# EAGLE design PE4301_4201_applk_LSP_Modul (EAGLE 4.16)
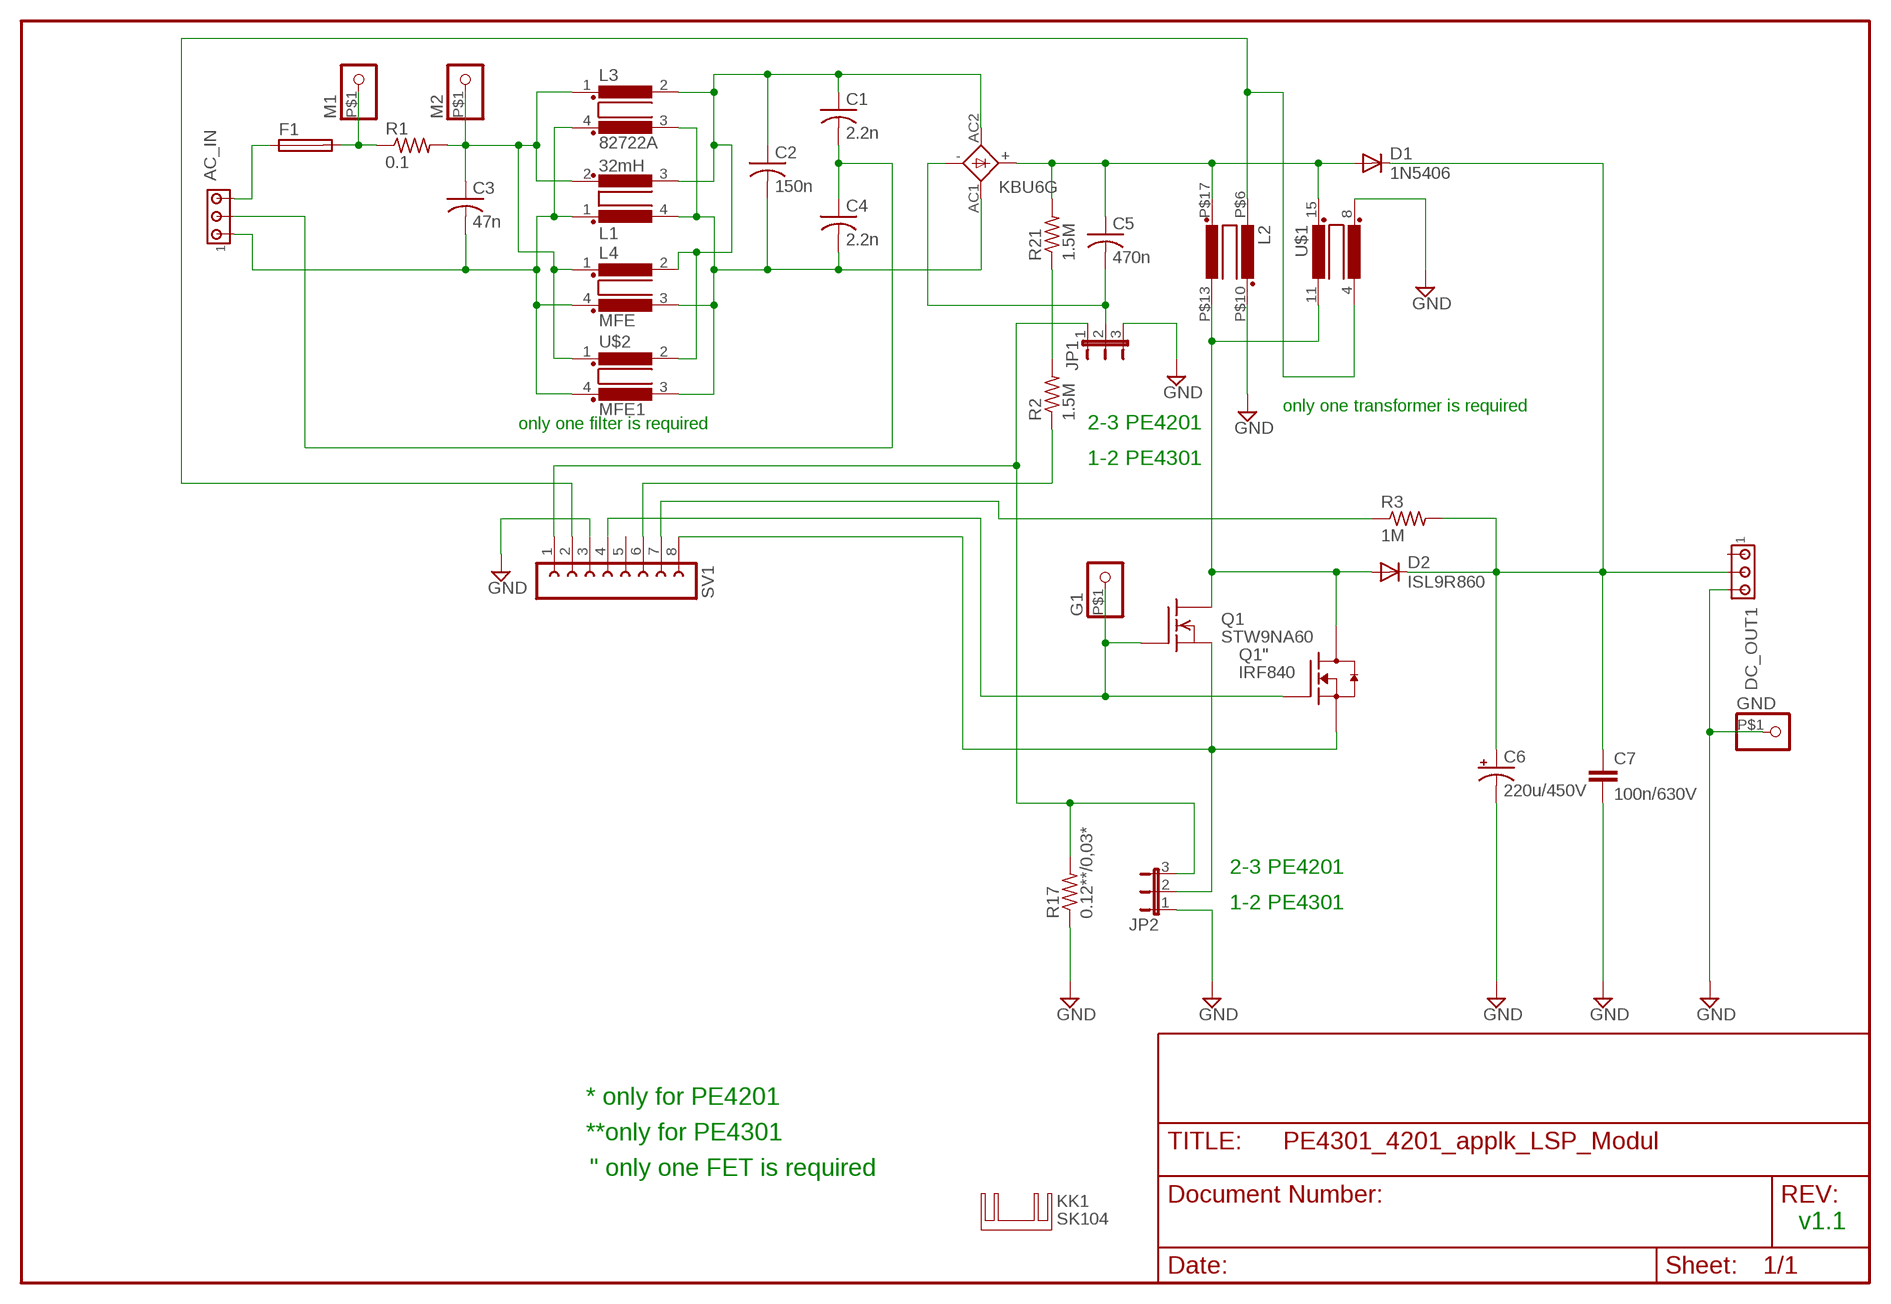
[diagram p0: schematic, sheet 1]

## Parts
AC_IN  KLEMME_3  [3MTA]
C1  2.2n  C2N2  [C2N2]
C2  150n  C-US150-084X183  [C150-084X183]
C3  47n  C-US102-064X133  [C102-064X133]
C4  2.2n  C2N2  [C2N2]
C5  470n  C-US150-084X183  [C150-084X183]
C6  220u/450V  CPOL-USE10-25  [EB25D]
C7  100n/630V  C15/6  [C15B6]
D1  1N5406  1N5624  [DO201-15]
D2  ISL9R860  BYT08P  [TO220ACS]
DC_OUT1  KLEMME_3  [3MTA]
F1  SH22,5A  [SH22,5A]
G1  PINHD  [LOETSTIFT]
GND  PINHD  [LOETSTIFT]
JP1  JP2E  [JP2]
JP2  JP2E  [JP2]
KBU6G  KBU  [KBU]
KK1  SK104  [SK104]
L1  32mH  VACT60405-R_2  [VACT60405-R]
L2  ETD49_SCH  [ETD49]
L3  82722A  [82722A]
L4  MFE  [MFE]
M1  PINHD  [LOETSTIFT]
M2  PINHD  [LOETSTIFT]
Q1  STW9NA60  FQA24N50  [TOP3V]
Q1"  IRF840  [TO220_V]
R1  0.1  R-US_0617/22  [0617/22]
R2  1.5M  R-US_0207/10  [0207/10]
R3  1M  R-US_0207/10  [0207/10]
R17  0.12**/0,03*  R-US_0617/22  [0617/22]
R21  1.5M  R-US_0207/10  [0207/10]
SV1  FE08-1  [FE08]
U$1  ETD39ETD39  [ETD29LS]
U$2  MFE1  [MFE1]

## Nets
B3: R3.1 SV1.7
GND: C6.- C7.2 DC_OUT1.3 GND.P$1 JP1.3 JP2.1 L2.P$10 R17.1 SV1.3 U$1.8
N$1: AC_IN.3 F1.1
N$2: AC_IN.1 C3.2 L1.1 L3.4 L4.4 U$2.4
N$3: C3.1 L1.2 L3.1 L4.1 M2.P$1 R1.2 U$2.1
N$4: C1.1 C2.1 KBU6G.AC2 L1.3 L3.2 L4.2 U$2.2
N$5: C2.2 C4.2 KBU6G.AC1 L1.4 L3.3 L4.3 U$2.3
N$6: R2.2 R21.1
N$7: R2.1 SV1.6
N$8: AC_IN.2 C1.2 C4.1
N$10: G1.P$1 Q1".1(G) Q1.G SV1.4
N$11: D2.A L2.P$13 Q1".2(D) Q1.D U$1.11
N$15: JP2.2 Q1".3(S) Q1.S SV1.8
N$17: C5.2 JP1.2 KBU6G.-
N$18: C6.+ C7.1 D1.C D2.C DC_OUT1.2 R3.2
N$20: F1.2 M1.P$1 R1.1
N$29: L2.P$6 SV1.2 U$1.4
N$30: C5.1 D1.A KBU6G.+ L2.P$17 R21.2 U$1.15
N$34: JP1.1 JP2.3 R17.2 SV1.1
Unconnected: DC_OUT1.1 SV1.5

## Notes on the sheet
- only one transformer is required
- only one filter is required | 2-3 PE4201
- 1-2 PE4301
- 2-3 PE4201
- 1-2 PE4301
- * only for PE4201
- **only for PE4301
- " only one FET is required
- v1.1

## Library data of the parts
AC_IN DC_OUT1 = PE4201:KLEMME_3: AMP connector
C1 C4 = PE4201:C2N2
C2 C3 C5 = rcl:C-US: CAPACITOR, American symbol
C6 = rcl:CPOL-US: POLARIZED CAPACITOR, American symbol
C7 = capacitor-wima:C: CAPACITOR
D1 = diode:1N5624: DIODE
D2 = diode:BYT08P: DIODE
F1 = fuse:SH22,5A: FUSE HOLDER
G1 GND M1 M2 = PE4201:PINHD: PIN HEADER
JP1 JP2 = jumper:JP2E: JUMPER
KBU6G = rectifier:KBU: DIOTEC RECTIFIER
KK1 = heatsink:SK104: HEATSINK
L1 = PE4201:VACT60405-R_2: FILTER
L2 = PE4201:ETD49_SCH
L3 = inductors:82722A: FILTER
L4 = inductors:MFE: FILTER
Q1 = PE4201:FQA24N50: N-Channel Enhancement MOSFET 400V; 12,5A; 0,4Ohm
Q1" = PE4201:IRF840
R1-R3 R17 R21 = rcl:R-US_: RESISTOR, American symbol
SV1 = con-lsta:FE08-1: FEMALE HEADER
U$1 = inductors:ETD39
U$2 = inductors:MFE1

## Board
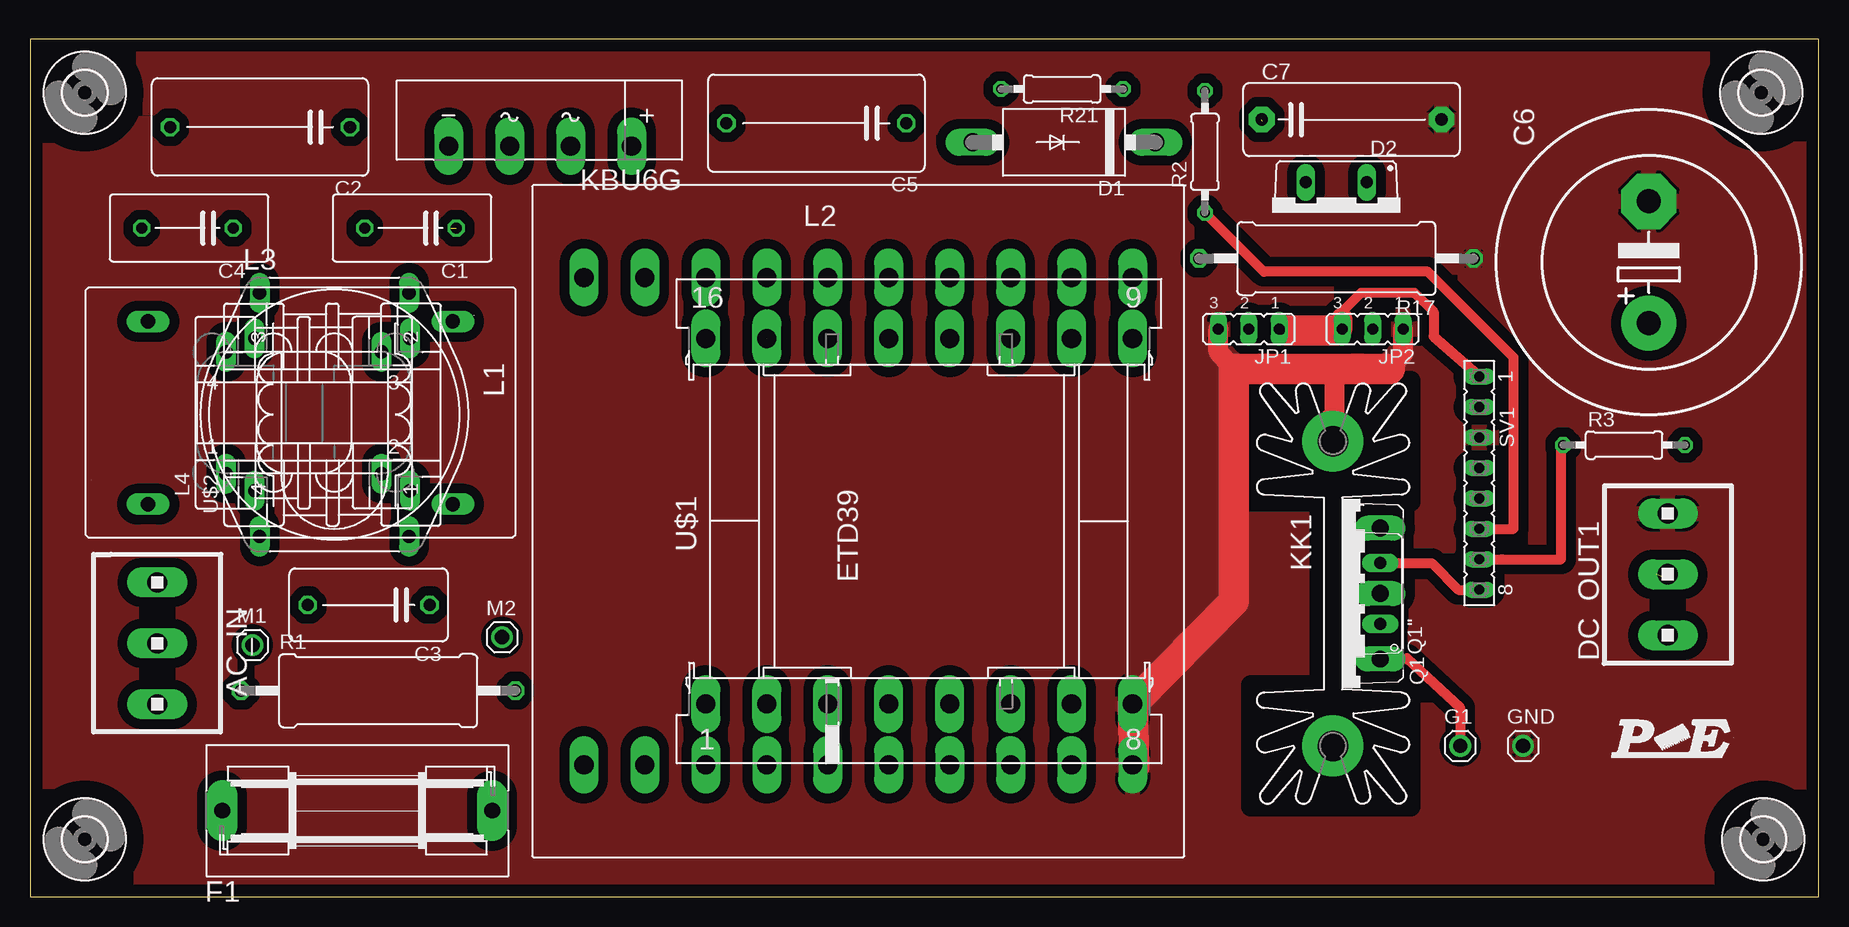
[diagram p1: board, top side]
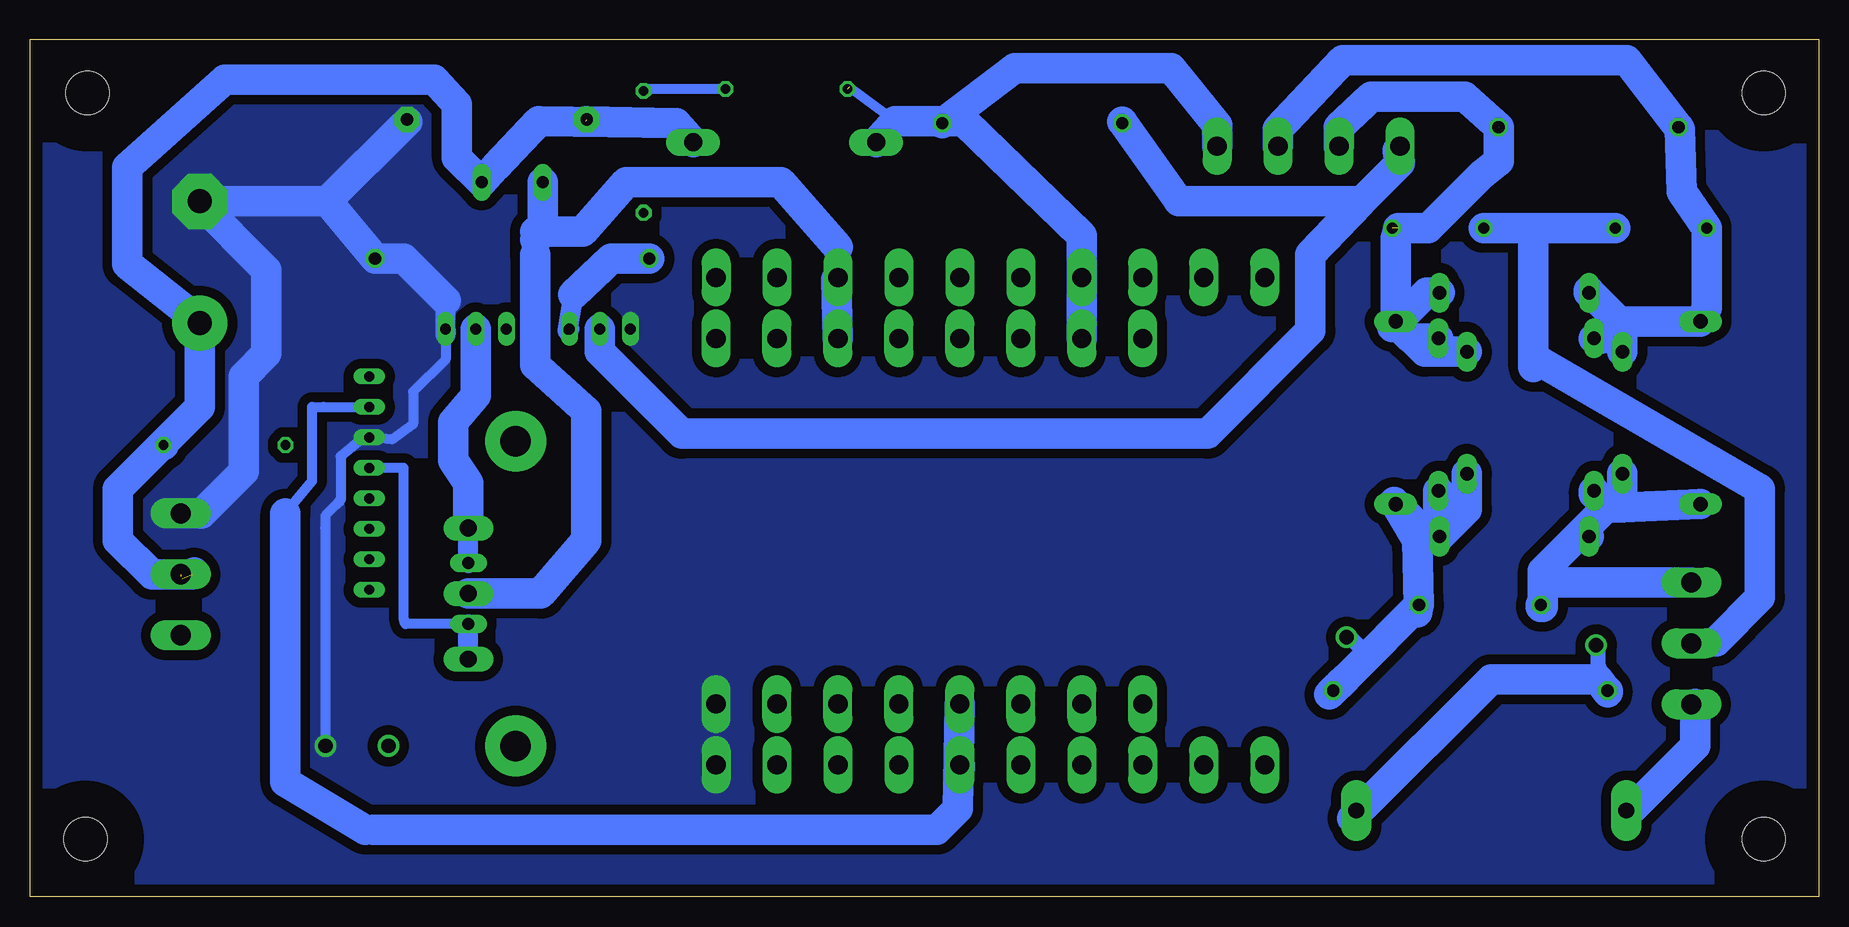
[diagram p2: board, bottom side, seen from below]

Size 149.05 x 71.48 mm. Coordinates in mm from the lower left corner, seen from the top.
Outline: 0,0 149.05,0 149.05,71.48 0,71.48 0,0
Copper layers (1*16): Top 0.035mm / dielectric 1.5mm / Bottom 0.035mm
Design rules "default": minimum track width 10mil, minimum drill 24mil, track to track 8mil, track to pad 8mil, pad to pad 8mil, via to via 8mil, smd to smd 8mil, copper to edge 40mil, drill to drill 8mil, minimum pad ring 10mil, minimum via ring 8mil, stop-mask expansion 4mil, vias tented up to drill 0mil, thermal gap 10mil

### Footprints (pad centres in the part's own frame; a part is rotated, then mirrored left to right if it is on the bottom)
3MTA = drill 1.676 long: 1 5.057,0; 2 -0.025,0; 3 -5.098,0
C2N2 = drill 0.914 octagon: 1 -3.81,0; 2 3.81,0
C150-084X183 = drill 1.016 octagon: 1 -7.493,0; 2 7.493,0
C102-064X133 = drill 1.016 octagon: 1 -5.08,0; 2 5.08,0
EB25D = drill 2.007 pad 4.597 round: + -5.08,0 | drill 2.007 pad 4.597 octagon: - 5.08,0
C15B6 = drill 1.016 pad 2.159 octagon: 1 -7.493,0; 2 7.493,0
DO201-15 = drill 1.499 long: A 7.62,0; C -7.62,0
TO220ACS = drill 1.016 long: A 2.54,-2.54; C -2.54,-2.54
SH22,5A = drill 1.321 pad 2.54 long: 1 -11.252,0; 2 11.252,0
LOETSTIFT = drill 1.2 round: P$1 0,0
JP2 = drill 0.914 long: 1 -2.54,0; 2 0,0; 3 2.54,0
KBU = drill 1.6 long: + -7.62,2.54; - 7.62,2.54; AC1 -2.54,2.54; AC2 2.54,2.54
SK104 = drill 2.54 pad 5.08 round: A2,5 -12.7,-0.762; B2,5 12.7,-0.762
VACT60405-R = drill 1.194 long: 1 12.983,7.624; 2 -12.413,7.624; 3 -12.413,-7.614; 4 12.983,-7.614
ETD49 = drill 1.6 long: P$1 15.24,-40.64; P$2 15.24,-35.56; P$3 15.24,-30.48; P$4 15.24,-25.4; P$5 15.24,-20.32; P$6 15.24,-15.24; P$7 15.24,-10.16; P$8 15.24,-5.08; P$9 15.24,0; P$10 15.24,5.08; P$11 -25.4,5.08; P$12 -25.4,0; P$13 -25.4,-5.08; P$14 -25.4,-10.16; P$15 -25.4,-15.24; P$16 -25.4,-20.32; P$17 -25.4,-25.4; P$18 -25.4,-30.48; P$19 -25.4,-35.56; P$20 -25.4,-40.64
82722A = drill 1.118 long: 1 10.16,6.223; 2 -10.16,6.223; 3 -10.16,-6.223; 4 10.16,-6.223
MFE = drill 1.118 long: 1 6.477,-5.08; 2 6.477,5.08; 3 -6.477,5.08; 4 -6.477,-5.08
TOP3V = drill 1.397 long: D 0,-3.175; G -5.461,-3.175; S 5.461,-3.175
TO220_V = drill 1.016 long: 1 -2.54,0; 2 0,0; 3 2.54,0
0617/22 = drill 1.016 octagon: 1 -11.43,0; 2 11.43,0
0207/10 = drill 0.813 octagon: 1 -5.08,0; 2 5.08,0
FE08 = drill 0.813 long: 1 -8.89,0; 2 -6.35,0; 3 -3.81,0; 4 -1.27,0; 5 1.27,0; 6 3.81,0; 7 6.35,0; 8 8.89,0
ETD29LS = drill 1.6 long: 1 -15.24,-17.78; 2 -10.16,-17.78; 3 -5.08,-17.78; 4 0,-17.78; 5 5.08,-17.78; 6 10.16,-17.78; 7 15.24,-17.78; 8 20.32,-17.78; 9 20.32,12.7; 10 15.24,12.7; 11 10.16,12.7; 12 5.08,12.7; 13 0,12.7; 14 -5.08,12.7; 15 -10.16,12.7; 16 -15.24,12.7; 25 5.08,-17.78
MFE1 = drill 1.118 long: 1 6.477,-6.35; 2 6.477,6.35; 3 -6.477,6.35; 4 -6.477,-6.35
3,6 = hole 3.6: 0,0

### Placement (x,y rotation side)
AC_IN  10.6,21.14 90 top
C1  31.71,55.74 180 top
C2  19.17,64.16 180 top
C3  28.22,24.31 180 top
C4  13.14,55.74 180 top
C5  65.53,64.47 180 top
C6  134.9,52.89 90 top
C7  110.13,64.79 0 top
D1  86.16,62.89 180 top
D2  108.86,57.01 180 top
DC_OUT1  136.49,26.85 270 top
F1  27.27,7.17 0 top
G1  119.18,12.56 0 top
GND  124.42,12.56 0 top
JP1  101.56,47.33 180 top
JP2  111.88,47.33 180 top
KBU6G  42.51,65.11 180 top
KK1  109.34,25.26 270 top
L1  22.82,40.34 180 top
L2  86.8,26.22 270 top
L3  25.36,40.19 270 top
L4  22.82,40.35 0 top
M1  18.54,20.98 0 top
M2  39.33,21.61 0 top
Q1  109.34,25.26 90 top
Q1"  112.52,25.26 90 top
R1  29.01,17.17 0 top
R2  97.91,62.09 90 top
R3  132.84,37.65 0 top
R17  108.86,53.2 180 top
R21  86,67.33 180 top
SV1  120.77,34.47 270 top
U$1  71.56,33.84 0 top
U$2  25.2,40.19 0 top
U$4  [LOGO]  132.52,10.98 0 top
U$5  [3,6]  144.27,67.02 0 top
U$6  [3,6]  4.57,67.02 0 top
U$7  [3,6]  4.57,4.79 0 top
U$8  [3,6]  144.43,4.79 0 top

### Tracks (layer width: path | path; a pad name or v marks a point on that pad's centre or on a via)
B3
  Top 0.813: 127.6,37.49 R3.1 127.6,37.65 127.6,37.49 | 127.6,28.12 122.68,28.12 SV1.7 | 127.6,28.12 | 127.6,37.49 | 127.6,28.12 127.6,37.49
GND
  Top 0.813: U$1.8 91.88,15.74 | 91.88,10.66 | 91.88,10.66 L2.P$10 | 91.88,10.66 92.04,10.82
  Top 1.676: JP1.3 99.02,45.43 100.29,44 | JP2.1 114.42,47.17 114.42,45.27 113.31,44 | 108.71,44 108.71,40.19 108.39,39.87
  Top 2.54: 113.31,44 108.71,44 100.29,44 100.29,24.63 U$1.8 92.04,10.82
  Bottom 0.813: U$1.8 91.88,15.74 | 114.42,47.17 JP2.1 114.42,44.79 117.12,42.09 117.12,39.39 118.87,38.12 SV1.3 121.25,38.28 123.15,36.69 123.15,33.2 123.15,33.04 123.47,32.73 124.42,31.77 124.42,30.66 124.42,30.82 GND.P$1
  Bottom 1.676: 114.42,46.85 | JP2.1 114.42,46.85 | 114.42,46.85 114.42,47.17 JP2.1 | JP2.1 114.42,49.71 | 117.63,64.6 C7.2 | C6.- 135.06,57.97
  Bottom 2.54: 124.26,57.97 R17.1 117.91,53.2 114.42,49.71 | 124.26,57.97 C6.- | 124.26,57.97 117.63,64.6 | 135.06,57.97 129.34,52.25 129.34,45.27 131.25,43.36 131.25,35.42 131.42,35.29 131.42,35.28 131.41,35.27 134.72,31.95 DC_OUT1.3
  pour Top (isolate 0.813): 0.28,71.46 148.55,71.46 arc90 148.87,71.78 148.87,0.34 arc90 149.03,0.18 0.12,0.18 0.12,71.3
  pour Bottom (isolate 0.813, no thermals): 0.12,71.46 148.87,71.46 149.19,71.14 149.19,0.02 149.03,0.18 0.12,0.18 0.12,71.3
N$1
  Bottom 1.27: AC_IN.3 10.3,16.04 10.28,16.06
  Bottom 2.54: F1.1 16.02,6.87 16,6.85 10.28,12.56 10.28,16.06
N$2
  Bottom 2.54: 22.98,24.31 C3.2 23.14,24.15 22.98,24.31 | AC_IN.1 22.98,26.19 22.98,24.31 | 22.98,24.31 22.98,24.15 | 17.75,32.4 16.3,32.46 | 16.3,32.46 L1.1 | 20.92,29.23 22.98,27.17 22.98,24.31 | 20.92,29.23 17.75,32.4 | 20.92,29.23 | L3.4 20.12,30.03 20.92,29.23 | 16.3,32.46 16.3,32.71 16.35,32.76 L4.4 | 17.75,32.4 17.75,32.56 17.74,32.57 18.73,33.55 U$2.4
N$3
  Bottom 1.27: 38.78,18.83 37.51,20.1 39.02,21.61 M2.P$1
  Bottom 2.54: C3.1 33.46,23.68 | C3.1 33.46,29.67 L1.2 35.24,32.76 | R1.2 39.97,17.64 39.33,18.28 40.76,16.85 38.78,18.83 C3.1 | 35.24,32.76 35.36,32.88 | 31.71,30.03 32.51,30.03 35.24,32.76 | L4.1 29.3,32.28 31.55,30.03 L3.1 31.71,30.03 | U$2.1 31.68,30.06 31.71,30.03
N$4  (2 unrouted)
  Bottom 1.676: KBU6G.AC2 39.65,62.41
  Bottom 2.54: L1.3 35.24,54.92 35.05,55.74 32.51,55.74 28.06,60.19 26.63,61.3 26.63,64.16 29.49,66.7 37.27,66.7 39.97,64.16 KBU6G.AC2 | L3.2 32.67,50.35 35.52,47.49 35.52,47.65 35.21,47.96 | 35.36,47.96 35.36,47.97 | 35.36,47.96 L1.3 | L4.2 32.82,45.43 35.05,47.65 | 35.05,47.65 35.36,47.96 | 35.05,47.65 35.24,47.84 L1.3 | U$2.2 33.94,46.54 35.05,47.65 | 35.21,47.96 35.21,47.97 | L1.3 35.21,47.96
N$5
  Bottom 1.676: C4.2 9.33,55.43 | L1.4 9.84,47.93
  Bottom 2.54: KBU6G.AC1 45.05,64 39.65,69.71 16,69.71 11.55,64 | 11.39,58.76 C4.2 9.33,49.08 9.84,47.93 16.31,47.93 | 11.39,58.76 | 11.39,58.76 11.55,64 | 19.14,50.47 19.17,50.51 | 19.14,50.47 L3.3 | 16.31,47.93 16.6,47.93 16.63,47.97 | 16.63,47.97 19.14,50.47 | 16.31,47.93 16.31,47.49 16.35,47.46 L4.3 | U$2.3 18.06,46.54 16.63,47.97 | C2.2 11.68,64.19 11.55,64 | 11.55,64
N$6
  Bottom 0.813: R2.2 | R21.1 97.91,67.33 R2.2
N$7
  Top 0.813: R2.1 102.83,52.09 116.49,52.09 116.8,51.78 123.63,44.95 123.63,30.66 SV1.6 | SV1.6
N$8
  Bottom 0.813: 23.78,44.95 23.78,44.16
  Bottom 1.27: AC_IN.2 10.6,21.14 8.54,21.3
  Bottom 2.54: 23.78,55.74 C4.1 | 23.78,55.74 C1.2 | 23.78,44.95 4.88,34 4.88,24.95 8.54,21.3 | 23.78,44.16 23.78,55.74
N$10
  Top 0.813: G1.P$1 119.18,15.74 114.74,19.87 112.83,19.87 112.52,20.18 Q1.G
  Bottom 0.813: Q1".1 117.76,22.72 117.91,23.2 117.91,35.74 SV1.4 | 112.52,20.18 112.52,19.87 Q1.G
  Bottom 1.676: 112.52,19.87 Q1".1
N$11
  Bottom 1.676: 81.88,51.46 L2.P$13 81.72,54.16 | 106.96,55.43 106.96,54.79 106.96,53.52 | Q1".2 112.68,25.42
  Bottom 2.54: U$1.11 81.88,51.46 | 81.72,54.16 86.48,59.55 99.34,59.55 102.99,55.43 106.96,55.43 | 106.96,53.52 106.96,44.31 102.67,40.5 102.67,29.71 106.48,25.26 Q1".2 | 106.96,54.79 | D2.A 106.33,55.43 106.96,54.79
N$15
  Top 0.813: SV1.8 119.03,25.58 116.8,27.8 Q1".3 112.52,27.65
  Bottom 0.813: 112.52,31.3 112.61,30.25 Q1.S
  Bottom 1.676: 112.52,31.3 | Q1".3 Q1.S 112.52,31.3
  Bottom 2.54: 112.52,31.3 112.52,34.47 113.79,36.38 113.79,39.55 111.88,41.77 JP2.2
N$17
  Bottom 1.676: 35.05,62.25 KBU6G.- | 58.03,64.6 C5.2
  Bottom 2.54: 38.06,57.97 34.89,61.14 35.05,62.25 | 38.06,57.97 53.3,57.97 58.03,64.6 | JP1.2 101.56,45.43 94.74,38.6 50.92,38.6 42.35,47.17 42.35,53.52 38.06,57.97
N$18  (3 unrouted)
  Bottom 1.676: 134.74,47.81 C6.+ | 136.49,26.69 136.35,26.51 | 102.67,64.63 102.99,64.32 | DC_OUT1.2
  Bottom 2.54: D1.C 95.21,64.48 | 95.21,64.48 106.64,64.63 110.29,60.82 D2.C 113.47,61.62 113.47,66.06 115.37,68.13 132.84,68.13 140.93,60.82 140.93,52.73 134.74,47.81 | 95.21,64.48 102.67,64.63 | C6.+ 134.9,40.82 137.92,37.81 | 137.92,37.81 141.73,34 141.73,29.71 138.87,26.85 135.54,26.85 135.38,27.01 | 137.92,37.81 R3.2
N$20
  Bottom 0.254: 38.38,7.01 | F1.2 38.52,7.01 38.38,7.01
  Bottom 1.27: 17.58,17.01 18.38,19.39 18.38,20.82 M1.P$1
  Bottom 2.54: R1.1 17.58,17.01 18.38,18.12 27.27,18.12 38.38,7.01 38.86,6.53
N$29
  Bottom 0.813: 71.56,10.66 | U$1.4 71.72,10.82 71.56,10.66 | 120.77,5.58 120.45,5.58 121.09,5.58 | 127.76,31.93 125.53,34.63 125.53,40.82 124.58,40.82 SV1.2
  Bottom 2.54: 71.56,10.66 L2.P$6 | U$1.4 71.72,7.33 73.46,5.58 120.45,5.58 | 121.09,5.58 127.76,9.55 127.76,31.93
N$30  (2 unrouted)
  Bottom 0.813: 80.77,67.49 79.5,66.54 76.96,64.63
  Bottom 1.676: L2.P$17 61.4,50.98 | L2.P$17 61.4,51.93 L2.P$17 | 71.24,64.51 C5.1 71.27,64.6 71.24,64.63 71.24,64.51
  Bottom 2.54: U$1.15 L2.P$17 | C5.1 66.99,69.08 53.94,69.08 50.13,64.32 KBU6G.+ | 61.4,51.93 61.4,55.11 71.24,64.63 76.96,64.63 D1.A | D1.A
N$34  (via drill 0.6)
  Top 0.813: 109.34,48.28 109.34,48.76 110.93,50.35 115.37,50.35 116.96,48.76 116.96,46.7 120.61,43.52 120.77,43.2 SV1.1 | SV1.1 120.93,43.36 | SV1.1
  Top 1.676: JP2.3 109.34,48.28 109.34,47.17 JP2.3 | v104.26,47.17 104.74,47.17 | 108.87,47.17 JP2.3
  Top 2.54: 104.74,47.17 108.87,47.17
  Bottom 1.676: JP1.1 v104.26,47.17 103.79,50.19
  Bottom 2.54: R17.2 100.61,53.2 103.79,50.19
